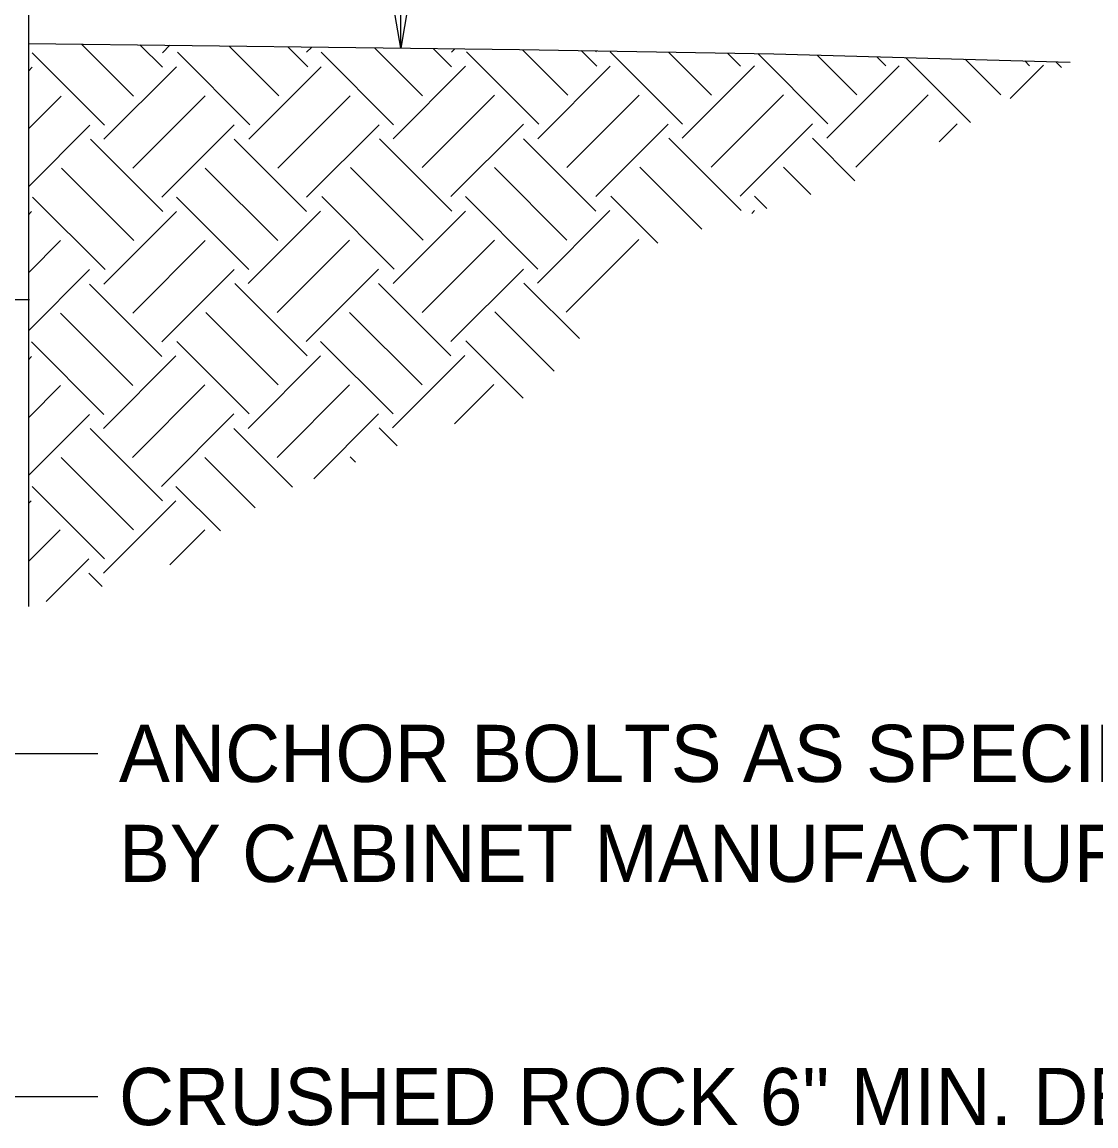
# Model space of a CAD drawing. Extents: x 99992 to 113392, y 99794 to 102182.
# Drawn here: x 112090.8 to 112316.4, y 101312.5 to 101544.3 of the extents above; entities that cross this region are included whole.
import ezdxf

# ---------------------------------------------------------------- set-up
doc = ezdxf.new("R2010")
doc.units = 0
doc.layers.add('Border Organizer Shape', color=7, linetype='Continuous')

msp = doc.modelspace()

# ---------------------------------------------------------------- linework, layer by layer
at = {"layer": 'Border Organizer Shape'}
for p, q in [((112170.37, 101538.8), (112170.37, 101583.38)), ((112092.16, 101572.04), (112092.16, 101421.58)), ((112092.16, 101539.78), (112195.32, 101538.49)), ((112103.29, 101539.65), (112114.23, 101528.7)), ((112115.61, 101539.49), (112120.31, 101534.78)), ((112120.31, 101537.83), (112121.9, 101539.41)), ((112134.32, 101539.25), (112144.76, 101528.81)), ((112092.94, 101537.83), (112108.15, 101522.61)), ((112123.47, 101537.94), (112138.68, 101522.73)), ((112146.64, 101539.1), (112150.84, 101534.89)), ((112150.62, 101537.93), (112151.73, 101539.04)), ((112153.67, 101537.93), (112168.88, 101522.72)), ((112164.89, 101538.87), (112174.96, 101528.81)), ((112177.21, 101538.72), (112181.04, 101534.89)), ((112181.04, 101537.93), (112181.77, 101538.66)), ((112184.2, 101538.05), (112199.41, 101522.83)), ((112195.32, 101538.49), (112248.79, 101537.61)), ((112195.93, 101538.48), (112205.49, 101528.92)), ((112208.29, 101538.28), (112211.57, 101535)), ((112211.35, 101538.04), (112211.54, 101538.22)), ((112214.4, 101538.04), (112229.6, 101522.83)), ((112226.62, 101537.98), (112235.69, 101528.91)), ((112239, 101537.77), (112241.77, 101535)), ((112245.41, 101537.66), (112260.13, 101522.94)), ((112248.79, 101537.61), (112311.03, 101535.86)), ((112257.89, 101537.35), (112266.22, 101529.02)), ((112270.41, 101537), (112272.3, 101535.11)), ((112092.16, 101534), (112092.94, 101534.78)), ((112108.04, 101519.68), (112123.25, 101534.89)), ((112138.46, 101519.68), (112153.67, 101534.89)), ((112168.77, 101519.78), (112183.98, 101535)), ((112199.19, 101519.78), (112214.4, 101535)), ((112229.5, 101519.89), (112244.71, 101535.1)), ((112259.91, 101519.89), (112275.12, 101535.1)), ((112276.44, 101536.83), (112290.11, 101523.16)), ((112288.95, 101536.48), (112296.42, 101529.02)), ((112298.44, 101528.22), (112305.43, 101535.21)), ((112301.48, 101536.13), (112302.5, 101535.1)), ((112307.97, 101535.94), (112309.18, 101534.73)), ((112092.16, 101521.83), (112099.02, 101528.7)), ((112114.13, 101513.6), (112129.33, 101528.81)), ((112144.54, 101513.6), (112159.75, 101528.81)), ((112174.86, 101513.71), (112190.07, 101528.91)), ((112205.27, 101513.71), (112220.48, 101528.91)), ((112235.58, 101513.81), (112250.79, 101529.02)), ((112266, 101513.81), (112281.21, 101529.02)), ((112298.44, 101528.22), (112298.44, 101528.22)), ((112092.16, 101509.67), (112105.1, 101522.61)), ((112120.21, 101507.51), (112135.42, 101522.72)), ((112150.62, 101507.51), (112165.83, 101522.72)), ((112180.94, 101507.62), (112196.15, 101522.83)), ((112211.35, 101507.62), (112226.56, 101522.83)), ((112241.67, 101507.73), (112256.88, 101522.94)), ((112283.5, 101519.15), (112287.29, 101522.94)), ((112105.22, 101519.68), (112120.43, 101504.48)), ((112135.42, 101519.68), (112150.62, 101504.47)), ((112165.95, 101519.79), (112181.15, 101504.58)), ((112196.15, 101519.78), (112211.35, 101504.58)), ((112226.67, 101519.9), (112241.88, 101504.69)), ((112256.88, 101519.89), (112265.8, 101510.96)), ((112159.86, 101513.71), (112175.07, 101498.5)), ((112190.07, 101513.71), (112205.27, 101498.49)), ((112220.59, 101513.82), (112233.62, 101500.79)), ((112250.79, 101513.81), (112256.56, 101508.04)), ((112099.13, 101513.6), (112114.34, 101498.39)), ((112129.33, 101513.6), (112144.54, 101498.39)), ((112093.05, 101507.52), (112108.26, 101492.31)), ((112123.25, 101507.51), (112138.46, 101492.31)), ((112153.78, 101507.63), (112168.99, 101492.41)), ((112183.98, 101507.62), (112199.19, 101492.41)), ((112214.51, 101507.73), (112224.37, 101497.87)), ((112244.71, 101507.73), (112247.32, 101505.11)), ((112092.16, 101503.8), (112092.83, 101504.47)), ((112108.04, 101489.26), (112123.25, 101504.47)), ((112138.36, 101489.37), (112153.56, 101504.58)), ((112168.77, 101489.37), (112183.98, 101504.58)), ((112199.08, 101489.48), (112214.29, 101504.68)), ((112244.14, 101504.11), (112244.71, 101504.68)), ((112092.16, 101491.63), (112098.91, 101498.39)), ((112114.13, 101483.18), (112129.33, 101498.39)), ((112144.44, 101483.29), (112159.65, 101498.49)), ((112174.86, 101483.29), (112190.07, 101498.49)), ((112205.17, 101483.39), (112220.37, 101498.6)), ((112092.16, 101479.46), (112105, 101492.31)), ((112120.21, 101477.1), (112135.42, 101492.31)), ((112150.52, 101477.2), (112165.72, 101492.41)), ((112180.94, 101477.2), (112196.15, 101492.41)), ((112105, 101489.26), (112120.21, 101474.05)), ((112135.53, 101489.38), (112150.74, 101474.17)), ((112165.72, 101489.37), (112180.94, 101474.16)), ((112196.26, 101489.48), (112207.92, 101477.82)), ((111662.78, 101486.01), (112092.39, 101486.01)), ((112098.91, 101483.18), (112114.13, 101467.97)), ((112129.44, 101483.29), (112144.66, 101468.08)), ((112159.65, 101483.29), (112174.86, 101468.08)), ((112190.17, 101483.4), (112202.62, 101470.95)), ((112092.83, 101477.1), (112108.04, 101461.89)), ((112123.36, 101477.21), (112138.57, 101462)), ((112153.56, 101477.2), (112168.77, 101462)), ((112184.09, 101477.31), (112196.07, 101465.34)), ((112092.16, 101473.38), (112092.83, 101474.05)), ((112107.94, 101458.95), (112123.15, 101474.16)), ((112138.36, 101458.95), (112153.56, 101474.16)), ((112168.67, 101459.06), (112183.87, 101474.26)), ((112092.16, 101461.21), (112098.91, 101467.97)), ((112114.02, 101452.87), (112129.23, 101468.08)), ((112144.44, 101452.87), (112159.65, 101468.08)), ((112181.67, 101459.9), (112189.96, 101468.19)), ((112092.16, 101449.04), (112105, 101461.89)), ((112120.1, 101446.79), (112135.31, 101462)), ((112152.12, 101448.39), (112165.72, 101462)), ((112105.11, 101458.96), (112120.32, 101443.75)), ((112135.31, 101458.95), (112147.64, 101446.63)), ((112165.84, 101459.06), (112169.63, 101455.27)), ((112099.03, 101452.87), (112114.24, 101437.66)), ((112129.23, 101452.87), (112139.81, 101442.28)), ((112159.76, 101452.98), (112160.9, 101451.84)), ((112092.94, 101446.79), (112108.15, 101431.58)), ((112123.15, 101446.79), (112132.52, 101437.42)), ((112092.16, 101443.18), (112092.73, 101443.74)), ((112107.94, 101428.53), (112123.15, 101443.74)), ((112092.16, 101431.01), (112098.81, 101437.66)), ((112121.9, 101430.34), (112129.23, 101437.66)), ((112095.9, 101422.58), (112104.89, 101431.58)), ((112104.89, 101428.53), (112107.67, 101425.76)), ((112070.88, 101390.72), (112106.73, 101390.72)), ((112070.88, 101318.67), (112106.73, 101318.67))]:
    msp.add_line(p, q, dxfattribs=at)
msp.add_lwpolyline([(112173.4, 101556.62), (112170.37, 101538.8), (112167.35, 101556.62), (112170.37, 101553.82)], close=True, dxfattribs=at)

# ---------------------------------------------------------------- texts
for s, p in [(' ANCHOR BOLTS AS SPECIFIED', (112106.73, 101384.72)), (' BY CABINET MANUFACTURER', (112106.73, 101363.72)), (' CRUSHED ROCK 6" MIN. DEPTH', (112106.73, 101312.67))]:
    msp.add_text(s, height=12, dxfattribs=at).set_placement(p)

doc.saveas('drawing.dxf')
